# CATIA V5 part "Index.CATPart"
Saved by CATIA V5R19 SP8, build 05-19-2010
Part number: Index
Bounding box of the stored display mesh (mm): x -70 to 0, y -20 to 20, z -12.5 to 38
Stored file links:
  C:\Users\rphgr\Desktop\0_Tapis_TC520B_vitesse\Index.CATPart
  C:\Users\rphgr\Desktop\0_Tapis_TC520B_vitesse\0_Tapis_TC520B_Conception.CATProduct
  D:\Documents\1_Travail\1 - ac-limoges.fr\ac-limoges.fr\Emmanuel Maynard - STI2D_Turgot\3 - Supports\Tapis de course TC520B\Tapis de course TC520B_Ca\Tapis.CATPart
  C:\Users\rphgr\Desktop\0_Tapis_TC520B_vitesse\Cadre Chasis (1).CATPart
  C:\Users\rphgr\Desktop\0_Tapis_TC520B_vitesse\Cadre Plateau.CATPart
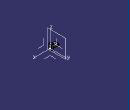
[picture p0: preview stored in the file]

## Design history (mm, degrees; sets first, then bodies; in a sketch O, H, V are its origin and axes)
AxisSystem1: origin (0, 0, 0), X (1, 0, 0), Y (0, 1, 0), Z (0, 0, 1)
Set1
  DatumSurface1 to DatumSurface3: linked copy from another document
  DatumCurve1: linked copy from another document
  DatumSurface4: linked copy from another document
Body1 (main body)
  Sketch1 on YZ plane of AxisSystem1, origin (0, 0, 0), H (0, 1, 0), V (0, 0, 1)
    line L1 (14, 18) -> (14, -12.5)
    line L2 (14, -12.5) -> (-14, -12.5)
    line L3 (-14, -12.5) -> (-14, 18)
    line L4 (-14, 18) -> (14, 18)
    construction line L5 (0, 0) -> (0, -5)
    point P5 (0, 0)
    line L6 (6, 0) -> (6, -5)
    line L7 (-6, -5) -> (-6, 0)
    arc A1 centre (0, -5) radius 6 from (6, -5) to (-6, -5) cw
    arc A2 centre (0, 0) radius 6 from (-6, 0) to (6, 0) cw
    distance L3 L1 = 28
    distance L5 L6 = 6
    length L5 = 5
    distance P5 O = 0
    distance P5 L2 = 12.5
    distance P5 L4 = 18
    vertical: L1 V, L3 V, L5 V
    horizontal: L2 H, L4 H
    equidistance: L1 L3 O
    coincidence: P5 V
    tangency: A1 L6, A2 L6, A1 L7, A2 L7
  Pad1: profile Sketch1, direction (-1, 0, 0), length 3
  Sketch2 on end face of Pad1, origin (-3, 0, 0), H (0, -1, 0), V (0, 0, 1)
    projected line E1 (-14, -12.5) -> (-14, 18) from edge [end face of Pad1 | face of Pad1 from Sketch1.L1]
    projected line E2 (-14, 18) -> (14, 18) from edge [end face of Pad1 | face of Pad1 from Sketch1.L4]
    projected line E3 (14, 18) -> (14, -12.5) from edge [end face of Pad1 | face of Pad1 from Sketch1.L3]
  Pad2: profile Sketch2, direction (-1, 0, 0), length 67, thin wall 5
  Sketch3 on face of Pad2, origin (0, 14, 0), H (-1, 0, 0), V (0, 0, 1)
    point P1 (15, -12.5)
    line L1 (15, -12.5) -> (15, -3)
    arc A1 centre (21, -3) radius 6 from (15, -3) to (21, 3) cw
    line L2 (21, 3) -> (70, 3)
    line L3 (70, 3) -> (70, -12.5)
    point P5 (70, -12.5)
    point P6 (70, -12.5)
    line L4 (70, -12.5) -> (21.4518, -12.5)
    reference intersected line E1 (18, -37) -> (18, -3) from face of DatumSurface2
    reference intersected line E2 (21, 0) -> (55, 0) from face of DatumSurface3
    reference projected line E3 (70, 7.5) -> (70, 12.5) from end face of Pad2
    reference intersected line E4 (63, -12.5) -> (3, -12.5) from face of Pad2
    reference projected arc E5 centre (21, -3) radius 3 from (21, 0) to (18, -3) ccw from edge of DatumCurve1
    distance L1 E1 = 3
    distance E2 L2 = 3
    distance A1 E5 = 3
    vertical: L1 V
    tangency: A1 L1, L2 A1
    coincidence: L4 P1, P6 P5, L3 E3, E4 L4
  Pocket1: profile Sketch3, direction (0, -1, 0), through (limit type 3)
  Sketch4 on face of Pad2, origin (0, -14, 0), H (1, 0, 0), V (0, 0, 1)
    reference projected curve E1 from face of Pad2
    line L1 (-17.233, 18) -> (-9.0605, -12.5)
    point P1 (-9.0605, -12.5)
    reference intersected line E3 through (-10.6127, -2.8437) direction (0.2588, -0.9659) from face of DatumSurface4
    line L2 (-15, -12.5) -> (-9.0605, -12.5)
    distance L1 E3 = 1
    coincidence: P1 E1
    horizontal: L2 H
  Pad3: profile Sketch4, direction (0, -1, 0), length 6
  Mirror1: of Pad3, about ZX plane of AxisSystem1
  Sketch5 on face of Mirror1, origin (0, 0, 18), H (1, 0, 0), V (0, 1, 0)
    line L1 (-17.233, 14) -> (-17.233, -14)
    vertical: L1 V
  Pad4: profile Sketch5, direction (0, 0, 1), length 20
  Fillet1: radius 2, on edge [face of Pad2 | start face of Pad1] (x2); edge [face of Pad2 | face of Pad2] (x4); edge [face of Pad2 | face of Pocket1 from Sketch3.L1] (x2); edge [face of Mirror1 | face of Mirror1] (x5); edge [face of Mirror1 | end face of Pad3] (x2); edge [face of Pad3 | face of Mirror1]; edge [face of Pad3 | end face of Pad3]; edge [face of Pad2 | face of Mirror1] (x3); edge [face of Mirror1 | face of Pad2]; edge [face of Pad2 | face of Pad3]; edge [face of Pad4 from Sketch5.L1 | face of Pad4]; edge [face of Pad4 | face of Pad4 from Sketch5.L1]; end face of Pad4
  Sketch6 on ZX plane of AxisSystem1, origin (0, 0, 0), H (0, 0, 1), V (1, 0, 0)
    line L1 (37.4142, -16.6472) -> (18, -45)
    point P1 (37.4142, -16.6472)
    point P2 (18, -45)
    reference intersected line E1 (18, 0) -> (18, -3) from face of Mirror1
    reference intersected line E2 (18, -70) -> (13, -70) from face of Mirror1
    reference projected point E3 (37.4142, -16.6472) from vertex [face of Fillet1 | face of Fillet1 | face of Fillet1]
    distance P2 E2 = 25
    coincidence: P2 E1, P1 E3
  Stiffener1: ThicknessValue 5, ExtendedProfile Sketch6, ThicknessTop 0
  Fillet2: radius 1, on face of Stiffener1 (x2); edge [face of Stiffener1 from Sketch6.L1 | face of Mirror1]
  Fillet3: radius 1, on edge [face of Mirror1 | face of Pad4 from Sketch5.L1] (x2)
  Body2
    Solid1: linked copy from another document
  Remove1: tool Body2
  Thickness1: Thickness -0.02, Face face of Solid1
Body3
  Plane1: type Offset, RefPlane face of Mirror1, Offset 5
  Sketch7 on Plane1, origin (-65, 0, 0), H (0, 1, 0), V (0, 0, 1)
    arc A1 centre (0, 0) radius 17.5 from (17.5, 0) to (-17.5, 0) ccw
    line L1 (17.5, 0) -> (-17.5, 0)
    point P1 (17.5, 0)
    radius A1 = 17.5
    coincidence: P1 H
    horizontal: L1 H
  Pad5: profile Sketch7, direction (1, 0, 0), length 5
  Sketch8 on start face of Pad5, origin (-65, 0, 0), H (0, -1, 0), V (0, 0, 1)
    circle A1 centre (0, 0) radius 14.5
    reference projected arc E1 centre (0, 0) radius 17.5 from (17.5, 0) to (-17.5, 0) ccw from edge [start face of Pad5 | face of Pad5 from Sketch7.A1]
    distance A1 E1 = 3
  Pocket2: profile Sketch8, direction (1, 0, 0), length 2
  Fillet4: radius 0.2, on start face of Pad5
  Mirror2: of the body so far, about end face of Pad5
